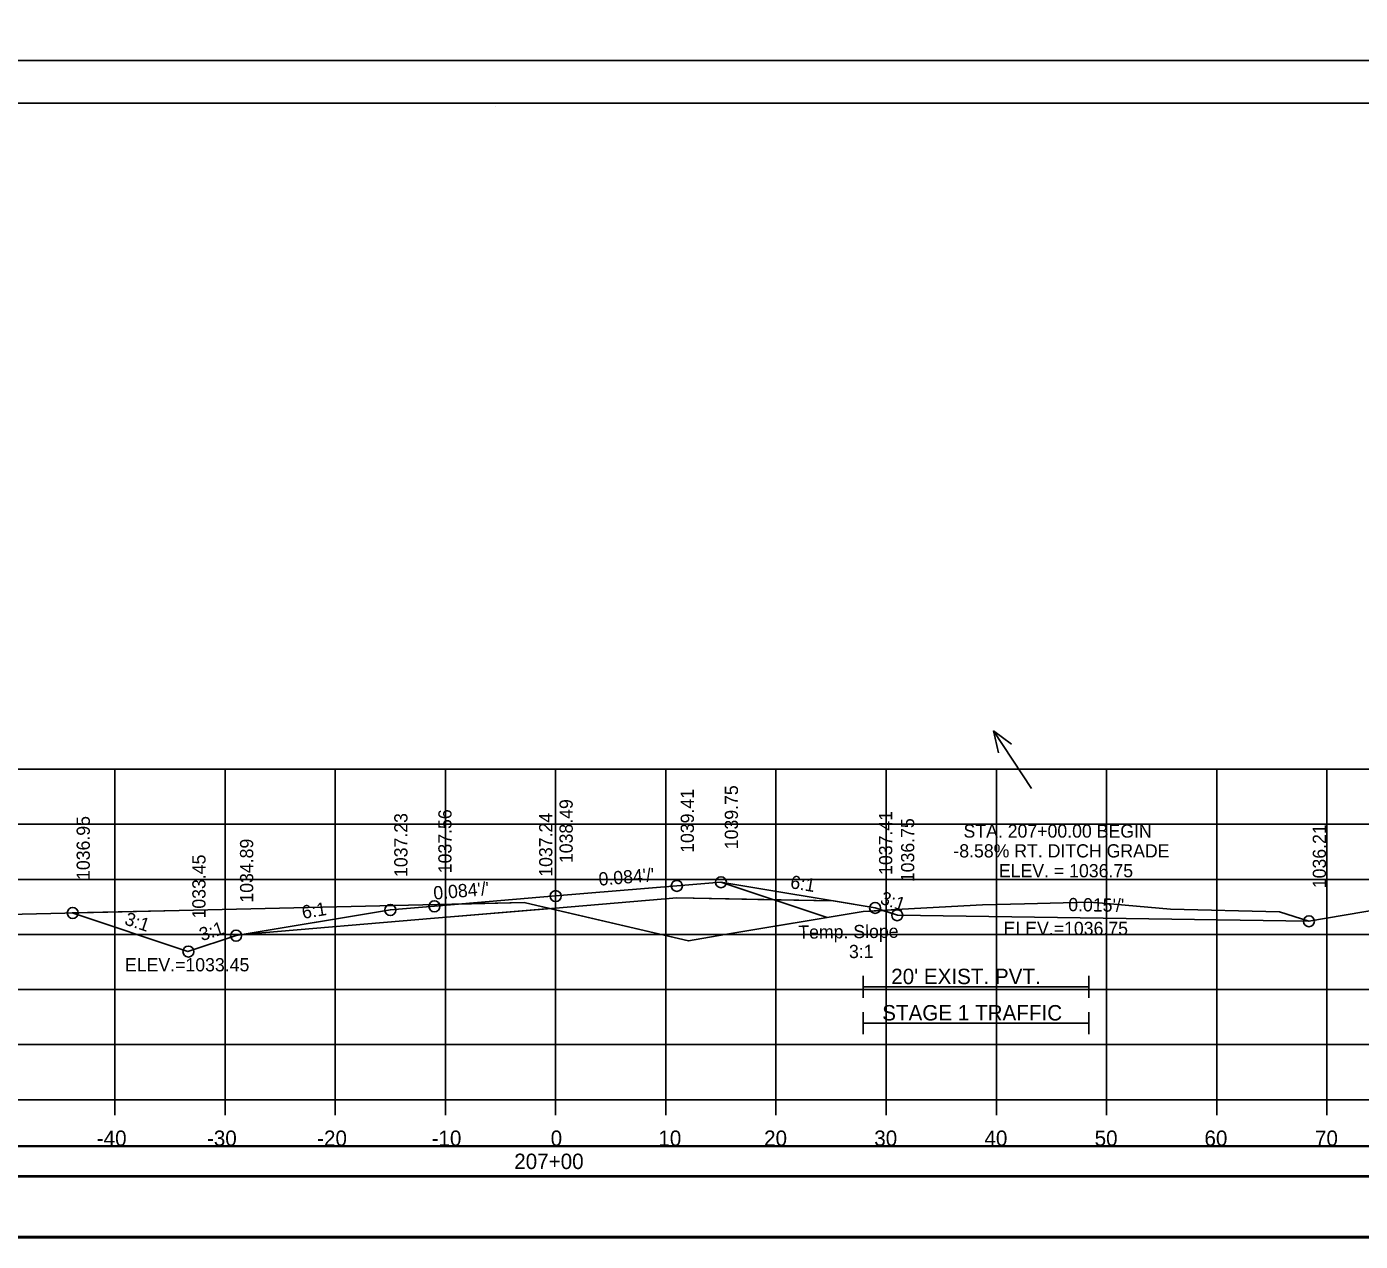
# Model space of a CAD drawing. Extents: x 1370565 to 1374448, y 301010 to 304637.
# Drawn here: x 1373320.8 to 1373441.8, y 301617.8 to 301728.1 of the extents above; entities that cross this region are included whole.
import ezdxf

# ---------------------------------------------------------------- set-up
doc = ezdxf.new("R2010")
doc.units = 0
for name, color, linetype in [('Default', 7, 'Continuous'), ('R_Alt Surface', 7, 'Continuous'), ('R_Axis', 7, 'Continuous'), ('R_Axis Annot', 7, 'Continuous'), ('R_Border', 7, 'Continuous'), ('R_Contours', 7, 'Continuous'), ('R_Drive', 7, 'Continuous'), ('R_Exist Surface', 7, 'Continuous'), ('R_Fin Surface', 7, 'Continuous'), ('R_Grid', 7, 'Continuous'), ('R_No Plot', 7, 'Continuous'), ('R_Water', 7, 'Continuous'), ('R_Water Annot', 7, 'Continuous'), ('R_Xsect Elev', 7, 'Continuous'), ('R_Xsect Slope', 7, 'Continuous')]:
    doc.layers.add(name, color=color, linetype=linetype)

msp = doc.modelspace()

# ---------------------------------------------------------------- linework, layer by layer
at = {"layer": 'Default'}
for points in [[(1373219.61, 301623.68), (1373518.02, 301623.68), (1373518.02, 301626.38), (1373219.61, 301626.38)], [(1373219.61, 301618.1), (1373518.02, 301618.1), (1373518.02, 301623.62), (1373219.61, 301623.62)]]:
    msp.add_lwpolyline(points, close=True, dxfattribs=at)
at = {"layer": 'R_Alt Surface'}
msp.add_lwpolyline([(1373340.71, 301645.68), (1373357.81, 301647.12), (1373368.81, 301648.04), (1373379.81, 301648.96), (1373394.04, 301648.68)], dxfattribs=at)
at = {"layer": 'R_Axis'}
for p, q in [((1373218.81, 301630.64), (1373518.81, 301630.64)), ((1373328.81, 301629.24), (1373328.81, 301630.64)), ((1373338.81, 301629.24), (1373338.81, 301630.64)), ((1373348.81, 301629.24), (1373348.81, 301630.64)), ((1373358.81, 301629.24), (1373358.81, 301630.64)), ((1373368.81, 301629.24), (1373368.81, 301630.64)), ((1373378.81, 301629.24), (1373378.81, 301630.64)), ((1373388.81, 301629.24), (1373388.81, 301630.64)), ((1373398.81, 301629.24), (1373398.81, 301630.64)), ((1373408.81, 301629.24), (1373408.81, 301630.64)), ((1373418.81, 301629.24), (1373418.81, 301630.64)), ((1373428.81, 301629.24), (1373428.81, 301630.64)), ((1373438.81, 301629.24), (1373438.81, 301630.64))]:
    msp.add_line(p, q, dxfattribs=at)
for points in [[(1373396.72, 301641.89), (1373396.72, 301639.89)], [(1373417.22, 301641.89), (1373417.22, 301639.89)], [(1373396.72, 301640.89), (1373417.22, 301640.89)], [(1373396.72, 301638.58), (1373396.72, 301636.58)], [(1373417.22, 301638.58), (1373417.22, 301636.58)], [(1373396.72, 301637.58), (1373417.22, 301637.58)]]:
    msp.add_lwpolyline(points, dxfattribs=at)
at = {"layer": 'R_Border'}
for p, q in [((1373210.81, 301721.1), (1373526.99, 301721.1)), ((1373363.33, 301720.84), (1373363.33, 301720.84)), ((1373363.33, 301720.84), (1373363.33, 301720.84))]:
    msp.add_line(p, q, dxfattribs=at)
at = {"layer": 'R_Contours'}
for p, q in [((1373360, 301648.4), (1373357.81, 301648.21)), ((1373379.81, 301648.96), (1373368.81, 301648.04)), ((1373388.64, 301648.79), (1373379.81, 301648.96)), ((1373393.44, 301647.19), (1373388.64, 301648.79)), ((1373394.04, 301648.68), (1373388.64, 301648.79)), ((1373388.64, 301648.79), (1373393.44, 301647.19)), ((1373368.81, 301648.04), (1373368.81, 301647.88)), ((1373398.51, 301647.83), (1373399.84, 301647.39)), ((1373399.84, 301647.39), (1373437.18, 301646.84))]:
    msp.add_line(p, q, dxfattribs=at)
for points in [[(1373360, 301648.4), (1373358.05, 301648.35), (1373334.63, 301647.81), (1373324.94, 301647.6)], [(1373353.81, 301647.88), (1373357.81, 301648.21), (1373360, 301648.4)], [(1373368.31, 301648), (1373367.63, 301648.16), (1373365.95, 301648.53), (1373360, 301648.4)], [(1373398.51, 301647.83), (1373397.81, 301648.06), (1373394.04, 301648.69)], [(1373394.04, 301648.69), (1373394.04, 301648.68)], [(1373437.18, 301646.84), (1373434.52, 301647.68), (1373424.61, 301647.93), (1373418.46, 301648.48), (1373417.22, 301648.58), (1373411.36, 301648.43), (1373407.54, 301648.34), (1373400.27, 301647.93), (1373398.51, 301647.83)], [(1373324.94, 301647.59), (1373335.44, 301644.09), (1373339.81, 301645.54), (1373340.71, 301645.69), (1373353.81, 301647.88)], [(1373324.94, 301647.6), (1373324.94, 301647.59)], [(1373357.81, 301648.21), (1373353.81, 301647.88), (1373340.71, 301645.69)], [(1373340.71, 301645.68), (1373357.81, 301647.12), (1373368.31, 301648)], [(1373368.81, 301647.88), (1373380.87, 301645.05), (1373384.16, 301645.65), (1373393.44, 301647.19)], [(1373393.44, 301647.19), (1373396.72, 301647.73), (1373398.51, 301647.83)], [(1373340.71, 301645.69), (1373340.71, 301645.68)]]:
    msp.add_lwpolyline(points, dxfattribs=at)
at = {"layer": 'R_Drive'}
for points in [[(1373219.61, 301623.73), (1373518.02, 301623.73), (1373518.02, 301626.44), (1373219.61, 301626.44)], [(1373219.61, 301618.21), (1373518.02, 301618.21), (1373518.02, 301623.73), (1373219.61, 301623.73)]]:
    msp.add_lwpolyline(points, close=True, dxfattribs=at)
at = {"layer": 'R_Exist Surface'}
msp.add_lwpolyline([(1373291.86, 301646.82), (1373334.63, 301647.81), (1373358.05, 301648.35), (1373365.95, 301648.53), (1373367.63, 301648.16), (1373380.87, 301645.05), (1373384.16, 301645.65), (1373396.72, 301647.73), (1373400.27, 301647.93), (1373407.54, 301648.34), (1373411.36, 301648.43), (1373417.22, 301648.58), (1373418.46, 301648.48), (1373424.61, 301647.93), (1373434.52, 301647.68), (1373437.18, 301646.84), (1373443.77, 301647.97), (1373449.18, 301648.78), (1373485.41, 301648.36), (1373494.54, 301648.23), (1373500.16, 301648.16), (1373518.81, 301647.89)], dxfattribs=at)
at = {"layer": 'R_Fin Surface'}
msp.add_line((1373383.81, 301650.4), (1373393.44, 301647.19), dxfattribs=at)
msp.add_lwpolyline([(1373324.94, 301647.59), (1373335.44, 301644.09), (1373339.81, 301645.54), (1373353.81, 301647.88), (1373357.81, 301648.21), (1373368.81, 301649.14), (1373379.81, 301650.06), (1373383.81, 301650.4), (1373397.81, 301648.06), (1373399.84, 301647.39), (1373437.18, 301646.84)], dxfattribs=at)
at = {"layer": 'R_Grid'}
for p, q in [((1373218.81, 301660.64), (1373518.81, 301660.64)), ((1373328.81, 301630.64), (1373328.81, 301660.64)), ((1373338.81, 301630.64), (1373338.81, 301660.64)), ((1373348.81, 301630.64), (1373348.81, 301660.64)), ((1373358.81, 301630.64), (1373358.81, 301660.64)), ((1373368.81, 301630.64), (1373368.81, 301660.64)), ((1373378.81, 301630.64), (1373378.81, 301660.64)), ((1373388.81, 301630.64), (1373388.81, 301660.64)), ((1373398.81, 301630.64), (1373398.81, 301660.64)), ((1373408.81, 301630.64), (1373408.81, 301660.64)), ((1373418.81, 301630.64), (1373418.81, 301660.64)), ((1373428.81, 301630.64), (1373428.81, 301660.64)), ((1373438.81, 301630.64), (1373438.81, 301660.64)), ((1373218.81, 301655.64), (1373518.81, 301655.64)), ((1373218.81, 301650.64), (1373518.81, 301650.64)), ((1373218.81, 301645.64), (1373518.81, 301645.64)), ((1373218.81, 301640.64), (1373518.81, 301640.64)), ((1373218.81, 301635.64), (1373518.81, 301635.64)), ((1373218.81, 301630.64), (1373518.81, 301630.64))]:
    msp.add_line(p, q, dxfattribs=at)
at = {"layer": 'R_No Plot'}
for p, q in [((1373198.41, 301725), (1373531.75, 301725)), ((1373198.41, 301724.99), (1373531.75, 301724.99))]:
    msp.add_line(p, q, dxfattribs=at)
for points in [[(1373198.41, 301938.33), (1373531.75, 301938.33), (1373531.75, 301724.99), (1373198.41, 301724.99)], [(1373198.41, 301724.99), (1373531.75, 301724.99), (1373531.75, 301511.65), (1373198.41, 301511.65)], [(1373444.73, 301721.1), (1373464.35, 301721.1), (1373464.35, 301711.22), (1373480.47, 301711.22), (1373503.67, 301711.22), (1373503.67, 301686.88), (1373526.99, 301686.88), (1373526.99, 301515.64), (1373210.81, 301515.64), (1373210.81, 301721.1)]]:
    msp.add_lwpolyline(points, close=True, dxfattribs=at)
for centre in [(1373383.81, 301650.38), (1373368.81, 301649.12), (1373379.81, 301650.05), (1373353.81, 301647.86), (1373357.81, 301648.2), (1373397.81, 301648.05), (1373324.98, 301647.59), (1373399.81, 301647.39), (1373437.18, 301646.84), (1373339.81, 301645.53), (1373335.48, 301644.09)]:
    msp.add_circle(centre, 0.5, dxfattribs=at)
at = {"layer": 'R_Water Annot'}
for p, q in [((1373412.01, 301658.89), (1373408.54, 301664.13)), ((1373408.54, 301664.13), (1373410.19, 301662.91)), ((1373408.54, 301664.13), (1373409.02, 301662.14))]:
    msp.add_line(p, q, dxfattribs=at)
at = {"layer": 'R_Xsect Elev'}
msp.add_line((1373368.81, 301647.88), (1373368.81, 301657.88), dxfattribs=at)

# ---------------------------------------------------------------- texts
at = {"layer": 'R_Axis Annot'}
for s, p in [("20' EXIST. PVT.", (1373399.27, 301641.13)), ('-40', (1373327.16, 301626.44)), ('-30', (1373337.16, 301626.44)), ('-20', (1373347.16, 301626.44)), ('-10', (1373357.55, 301626.44)), ('0', (1373368.36, 301626.44)), ('10', (1373378.13, 301626.44)), ('20', (1373387.73, 301626.44)), ('30', (1373397.73, 301626.44)), ('40', (1373407.73, 301626.44)), ('50', (1373417.73, 301626.44)), ('60', (1373427.7, 301626.44)), ('70', (1373437.73, 301626.44)), ('207+00', (1373365.05, 301624.34))]:
    msp.add_text(s, height=1.4, dxfattribs=at).set_placement(p)
at = {"layer": 'R_Water'}
msp.add_text('STAGE 1 TRAFFIC', height=1.4, dxfattribs=at).set_placement((1373398.45, 301637.83))
at = {"layer": 'R_Xsect Elev'}
for s, p in [('1039.41', (1373381.36, 301653.05)), ('1039.75', (1373385.36, 301653.38)), ('1037.56', (1373359.36, 301651.2)), ('1038.49', (1373370.36, 301652.12)), ('1037.41', (1373399.36, 301651.05)), ('1036.95', (1373326.53, 301650.59)), ('1037.23', (1373355.36, 301650.86)), ('1037.24', (1373368.51, 301650.88)), ('1036.75', (1373401.36, 301650.39)), ('1036.21', (1373438.73, 301649.84)), ('1034.89', (1373341.36, 301648.53)), ('1033.45', (1373337.03, 301647.09))]:
    msp.add_text(s, height=1.2, rotation=90, dxfattribs=at).set_placement(p)
for s, p in [('STA. 207+00.00 BEGIN ', (1373405.83, 301654.43)), ('-8.58% RT. DITCH GRADE', (1373404.91, 301652.63)), ('ELEV. = 1036.75', (1373409.04, 301650.83)), ('ELEV.=1036.75', (1373409.47, 301645.59)), ('ELEV.=1033.45', (1373329.72, 301642.29))]:
    msp.add_text(s, height=1.2, dxfattribs=at).set_placement(p)
at = {"layer": 'R_Xsect Slope'}
for s, rotation, p in [("0.084'/'", 4.8016, (1373372.76, 301650.06)), ('6:1', 350.5377, (1373390.05, 301649.85)), ("0.084'/'", 4.8016, (1373357.76, 301648.8)), ('3:1', 341.5651, (1373398.18, 301648.46)), ('6:1', 9.4623, (1373345.88, 301647.05)), ("0.015'/'", 359.1666, (1373415.33, 301647.76)), ('3:1', 341.5668, (1373329.6, 301646.57)), ('3:1', 18.4349, (1373336.7, 301645.02)), ('Temp. Slope ', 0.5536, (1373390.84, 301645.25)), ('3:1', 0.5536, (1373395.44, 301643.49))]:
    msp.add_text(s, height=1.2, rotation=rotation, dxfattribs=at).set_placement(p)

doc.saveas('drawing.dxf')
